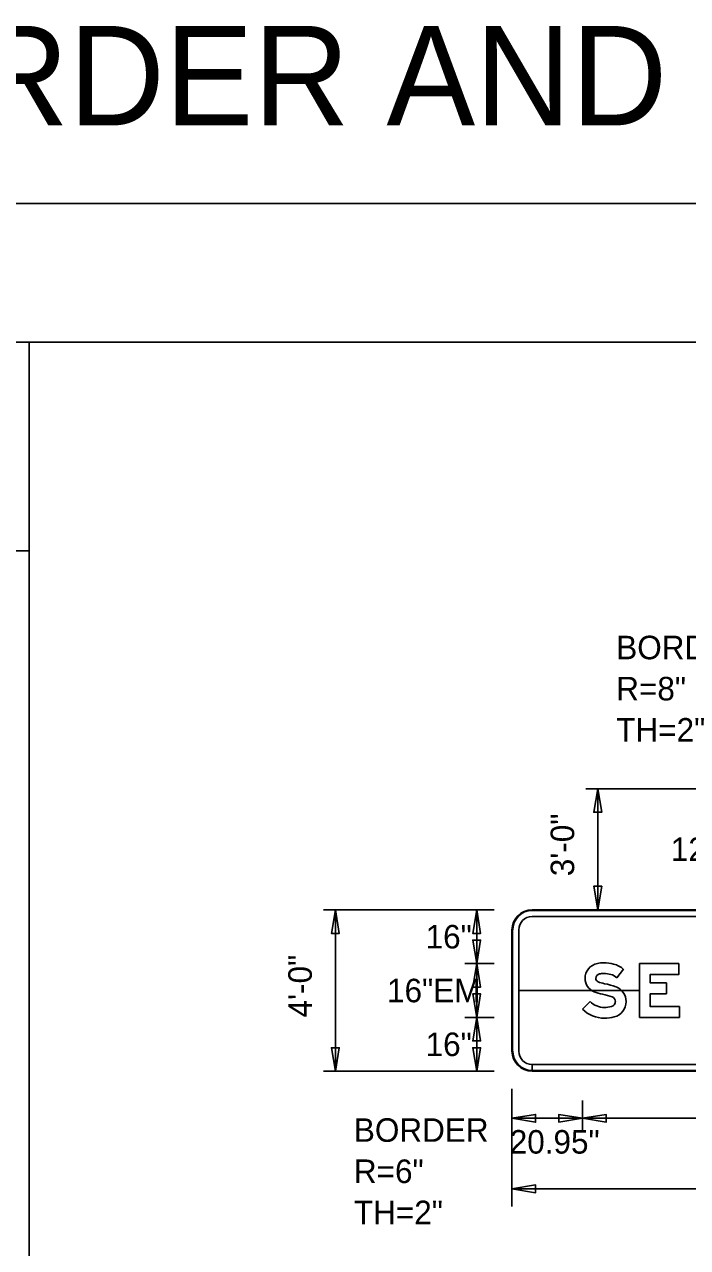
# Model space of a CAD drawing. Extents: x 2149934 to 2150188, y 145114 to 145238.
# Drawn here: x 2150076.2 to 2150092.63, y 145194.08 to 145224.38 of the extents above; entities that cross this region are included whole.
import ezdxf

# ---------------------------------------------------------------- set-up
doc = ezdxf.new("R2010")
doc.units = 0
for name, color, linetype in [('BORDER', 7, 'Continuous'), ('GSBWFILL', 7, 'Continuous'), ('GSCOLORFILL', 7, 'Continuous'), ('GSDIMS', 7, 'Continuous'), ('GSOUTLINE', 7, 'Continuous'), ('Level 1', 7, 'Continuous'), ('NON-PLOT', 7, 'Continuous'), ('PDF', 7, 'Continuous'), ('TEXT', 7, 'Continuous')]:
    doc.layers.add(name, color=color, linetype=linetype)

msp = doc.modelspace()

# ---------------------------------------------------------------- linework, layer by layer
at = {"layer": 'BORDER'}
for p, q in [((2150010.458, 145219.948), (2150174.061, 145219.948)), ((2150171.536, 145216.512), (2150017.557, 145216.512))]:
    msp.add_line(p, q, dxfattribs=at)
at = {"layer": 'GSBWFILL'}
for p, q in [((2150107.279, 145202.445), (2150088.779, 145202.445)), ((2150088.779, 145202.278), (2150107.279, 145202.278)), ((2150088.279, 145201.945), (2150088.279, 145198.945)), ((2150088.445, 145198.945), (2150088.445, 145201.945)), ((2150088.779, 145198.445), (2150088.779, 145198.611)), ((2150107.279, 145198.611), (2150088.78, 145198.611)), ((2150088.78, 145198.611), (2150088.78, 145198.445)), ((2150088.78, 145198.445), (2150107.279, 145198.445))]:
    msp.add_line(p, q, dxfattribs=at)
for points in [[(2150090.879, 145200.759), (2150091.044, 145200.97)], [(2150090.214, 145200.17), (2150090.026, 145199.981)]]:
    msp.add_lwpolyline(points, dxfattribs=at)
msp.add_lwpolyline([(2150092.413, 145201.111), (2150092.413, 145200.845), (2150091.706, 145200.845), (2150091.706, 145200.631), (2150092.106, 145200.631), (2150092.106, 145200.365), (2150091.706, 145200.365), (2150091.706, 145200.045), (2150092.426, 145200.045), (2150092.426, 145199.778), (2150091.439, 145199.778), (2150091.439, 145201.111)], close=True, dxfattribs=at)
for centre, radius, start, end in [((2150088.779, 145201.945), 0.5, 90, 180), ((2150088.779, 145201.945), 0.333, 90, 180), ((2150088.779, 145198.945), 0.5, 180, 270), ((2150088.779, 145198.945), 0.333, 180, 270)]:
    msp.add_arc(centre, radius, start, end, dxfattribs=at)
for centre, major_axis, start_param, end_param in [((2150090.471, 145200.742), (0, 0.382), 0.202758, 1.570796), ((2150090.553, 145200.347), (0, 0.785), 0, 0.202758), ((2150090.553, 145200.169), (0, 0.963), 6.026234, 6.283185), ((2150090.642, 145200.509), (0, 0.611), 5.565152, 6.026234), ((2150090.443, 145200.742), (0, 0.354), 1.570796, 2.761249), ((2150090.471, 145200.742), (0, 0.115), 0.202758, 1.570796), ((2150090.443, 145200.742), (0, 0.0872), 1.570796, 2.761249), ((2150090.734, 145201.469), (0, 0.87), 2.761249, 2.95744), ((2150090.553, 145200.347), (0, 0.519), 0, 0.202758), ((2150090.553, 145200.169), (0, 0.697), 6.026234, 6.283185), ((2150090.277, 145199.018), (0, 1.623), 5.918637, 6.099033), ((2150090.642, 145200.509), (0, 0.345), 5.523837, 6.026234), ((2150090.734, 145201.469), (0, 1.137), 2.761249, 2.95744), ((2150090.277, 145199.018), (0, 1.357), 5.918637, 6.099033), ((2150090.718, 145200.172), (0, 0.388), 4.712389, 5.918637), ((2150090.569, 145200.528), (0, 0.504), 2.360607, 3.141593), ((2150090.569, 145200.702), (0, 0.678), 3.141593, 3.401517), ((2150090.71, 145200.172), (0, 0.129), 3.401517, 4.712389), ((2150090.718, 145200.172), (0, 0.122), 4.712389, 5.918637), ((2150090.71, 145200.172), (0, 0.396), 3.401517, 4.712389), ((2150090.569, 145200.528), (0, 0.771), 2.360607, 3.141593), ((2150090.569, 145200.702), (0, 0.945), 3.141593, 3.401517)]:
    msp.add_ellipse(centre, major_axis=major_axis, ratio=0.999996, start_param=start_param, end_param=end_param, dxfattribs=at)
at = {"layer": 'GSCOLORFILL'}
for p, q in [((2150107.279, 145202.445), (2150088.779, 145202.445)), ((2150107.279, 145202.445), (2150088.779, 145202.445)), ((2150107.279, 145202.445), (2150088.779, 145202.445)), ((2150088.779, 145202.428), (2150107.279, 145202.428)), ((2150088.779, 145202.278), (2150107.279, 145202.278)), ((2150088.279, 145201.945), (2150088.279, 145198.945)), ((2150088.279, 145201.945), (2150088.279, 145198.945)), ((2150088.279, 145201.945), (2150088.279, 145198.945)), ((2150088.295, 145198.945), (2150088.295, 145201.945)), ((2150088.445, 145198.945), (2150088.445, 145201.945)), ((2150088.779, 145198.445), (2150088.779, 145198.611)), ((2150107.279, 145198.611), (2150088.78, 145198.611)), ((2150088.78, 145198.611), (2150088.78, 145198.445)), ((2150088.779, 145198.445), (2150088.779, 145198.461)), ((2150107.279, 145198.461), (2150088.779, 145198.461)), ((2150088.779, 145198.461), (2150088.779, 145198.445)), ((2150088.779, 145198.445), (2150107.279, 145198.445)), ((2150088.779, 145198.445), (2150107.279, 145198.445)), ((2150088.78, 145198.445), (2150107.279, 145198.445))]:
    msp.add_line(p, q, dxfattribs=at)
for points in [[(2150090.879, 145200.759), (2150091.044, 145200.97)], [(2150090.214, 145200.17), (2150090.026, 145199.981)]]:
    msp.add_lwpolyline(points, dxfattribs=at)
msp.add_lwpolyline([(2150092.413, 145201.111), (2150092.413, 145200.845), (2150091.706, 145200.845), (2150091.706, 145200.631), (2150092.106, 145200.631), (2150092.106, 145200.365), (2150091.706, 145200.365), (2150091.706, 145200.045), (2150092.426, 145200.045), (2150092.426, 145199.778), (2150091.439, 145199.778), (2150091.439, 145201.111)], close=True, dxfattribs=at)
for centre, radius, start, end in [((2150088.779, 145201.945), 0.5, 90, 180), ((2150088.779, 145201.945), 0.5, 90, 180), ((2150088.779, 145201.945), 0.5, 90, 180), ((2150088.779, 145201.945), 0.483, 90, 180), ((2150088.779, 145201.945), 0.333, 90, 180), ((2150088.779, 145198.945), 0.5, 180, 270), ((2150088.779, 145198.945), 0.5, 180, 270), ((2150088.779, 145198.945), 0.5, 180, 270), ((2150088.779, 145198.945), 0.483, 180, 270), ((2150088.779, 145198.945), 0.333, 180, 270)]:
    msp.add_arc(centre, radius, start, end, dxfattribs=at)
for centre, major_axis, start_param, end_param in [((2150090.471, 145200.742), (0, 0.382), 0.202758, 1.570796), ((2150090.553, 145200.347), (0, 0.785), 0, 0.202758), ((2150090.553, 145200.169), (0, 0.963), 6.026234, 6.283185), ((2150090.642, 145200.509), (0, 0.611), 5.565152, 6.026234), ((2150090.443, 145200.742), (0, 0.354), 1.570796, 2.761249), ((2150090.471, 145200.742), (0, 0.115), 0.202758, 1.570796), ((2150090.443, 145200.742), (0, 0.0872), 1.570796, 2.761249), ((2150090.734, 145201.469), (0, 0.87), 2.761249, 2.95744), ((2150090.553, 145200.347), (0, 0.519), 0, 0.202758), ((2150090.553, 145200.169), (0, 0.697), 6.026234, 6.283185), ((2150090.277, 145199.018), (0, 1.623), 5.918637, 6.099033), ((2150090.642, 145200.509), (0, 0.345), 5.523837, 6.026234), ((2150090.734, 145201.469), (0, 1.137), 2.761249, 2.95744), ((2150090.277, 145199.018), (0, 1.357), 5.918637, 6.099033), ((2150090.718, 145200.172), (0, 0.388), 4.712389, 5.918637), ((2150090.569, 145200.528), (0, 0.504), 2.360607, 3.141593), ((2150090.569, 145200.702), (0, 0.678), 3.141593, 3.401517), ((2150090.71, 145200.172), (0, 0.129), 3.401517, 4.712389), ((2150090.718, 145200.172), (0, 0.122), 4.712389, 5.918637), ((2150090.71, 145200.172), (0, 0.396), 3.401517, 4.712389), ((2150090.569, 145200.528), (0, 0.771), 2.360607, 3.141593), ((2150090.569, 145200.702), (0, 0.945), 3.141593, 3.401517)]:
    msp.add_ellipse(centre, major_axis=major_axis, ratio=0.999996, start_param=start_param, end_param=end_param, dxfattribs=at)
at = {"layer": 'GSDIMS'}
for p, q in [((2150090.841, 145205.445), (2150090.112, 145205.445)), ((2150090.403, 145202.445), (2150090.403, 145205.445)), ((2150094.341, 145205.445), (2150090.841, 145205.445)), ((2150084.341, 145202.445), (2150083.612, 145202.445)), ((2150083.904, 145198.445), (2150083.904, 145202.445)), ((2150087.841, 145202.445), (2150084.341, 145202.445)), ((2150087.841, 145202.445), (2150087.112, 145202.445)), ((2150087.404, 145201.111), (2150087.404, 145202.445)), ((2150090.841, 145202.445), (2150090.112, 145202.445)), ((2150094.341, 145202.445), (2150090.841, 145202.445)), ((2150087.841, 145201.111), (2150087.112, 145201.111)), ((2150087.841, 145201.111), (2150087.112, 145201.111)), ((2150087.404, 145201.111), (2150087.404, 145199.778)), ((2150087.841, 145199.778), (2150087.112, 145199.778)), ((2150087.841, 145199.778), (2150087.112, 145199.778)), ((2150087.404, 145198.445), (2150087.404, 145199.778)), ((2150084.341, 145198.445), (2150083.612, 145198.445)), ((2150087.841, 145198.445), (2150084.341, 145198.445)), ((2150087.841, 145198.445), (2150087.112, 145198.445)), ((2150088.279, 145198.007), (2150088.279, 145195.091)), ((2150088.279, 145197.716), (2150088.279, 145196.986)), ((2150090.026, 145197.716), (2150090.026, 145196.986)), ((2150090.026, 145197.716), (2150090.026, 145196.986)), ((2150088.279, 145197.278), (2150090.026, 145197.278)), ((2150090.026, 145197.278), (2150106.031, 145197.278)), ((2150088.279, 145195.966), (2150088.279, 145195.236)), ((2150088.279, 145195.528), (2150107.779, 145195.528))]:
    msp.add_line(p, q, dxfattribs=at)
for points in [[(2150090.403, 145205.445), (2150090.501, 145204.862), (2150090.306, 145204.862)], [(2150090.403, 145202.445), (2150090.501, 145203.028), (2150090.306, 145203.028)], [(2150083.904, 145202.445), (2150084.001, 145201.861), (2150083.806, 145201.861)], [(2150087.404, 145202.445), (2150087.501, 145201.861), (2150087.306, 145201.861)], [(2150087.404, 145201.111), (2150087.501, 145201.695), (2150087.306, 145201.695)], [(2150087.404, 145201.111), (2150087.501, 145200.528), (2150087.306, 145200.528)], [(2150087.404, 145199.778), (2150087.501, 145200.361), (2150087.306, 145200.361)], [(2150087.404, 145199.778), (2150087.501, 145199.195), (2150087.306, 145199.195)], [(2150083.904, 145198.445), (2150084.001, 145199.028), (2150083.806, 145199.028)], [(2150087.404, 145198.445), (2150087.501, 145199.028), (2150087.306, 145199.028)], [(2150088.279, 145197.278), (2150088.862, 145197.375), (2150088.862, 145197.181)], [(2150090.026, 145197.278), (2150089.443, 145197.375), (2150089.443, 145197.181)], [(2150090.026, 145197.278), (2150090.609, 145197.375), (2150090.609, 145197.181)], [(2150088.279, 145195.528), (2150088.862, 145195.625), (2150088.862, 145195.431)]]:
    msp.add_lwpolyline(points, close=True, dxfattribs=at)
at = {"layer": 'GSOUTLINE'}
for p, q in [((2150107.279, 145202.445), (2150088.779, 145202.445)), ((2150107.279, 145202.278), (2150088.779, 145202.278)), ((2150088.279, 145201.945), (2150088.279, 145198.945)), ((2150088.445, 145201.945), (2150088.445, 145198.945)), ((2150088.779, 145198.611), (2150107.279, 145198.611)), ((2150088.779, 145198.445), (2150107.279, 145198.445))]:
    msp.add_line(p, q, dxfattribs=at)
for points in [[(2150090.879, 145200.759), (2150091.044, 145200.97)], [(2150090.214, 145200.17), (2150090.026, 145199.981)]]:
    msp.add_lwpolyline(points, dxfattribs=at)
msp.add_lwpolyline([(2150092.413, 145201.111), (2150092.413, 145200.845), (2150091.706, 145200.845), (2150091.706, 145200.631), (2150092.106, 145200.631), (2150092.106, 145200.365), (2150091.706, 145200.365), (2150091.706, 145200.045), (2150092.426, 145200.045), (2150092.426, 145199.778), (2150091.439, 145199.778), (2150091.439, 145201.111)], close=True, dxfattribs=at)
for centre, radius, start, end in [((2150088.779, 145201.945), 0.5, 90, 180), ((2150088.779, 145201.945), 0.333, 90, 180), ((2150088.779, 145198.945), 0.5, 180, 270), ((2150088.779, 145198.945), 0.333, 180, 270)]:
    msp.add_arc(centre, radius, start, end, dxfattribs=at)
for centre, major_axis, start_param, end_param in [((2150090.471, 145200.742), (0, 0.382), 0.202758, 1.570796), ((2150090.553, 145200.347), (0, 0.785), 0, 0.202758), ((2150090.553, 145200.169), (0, 0.963), 6.026234, 6.283185), ((2150090.642, 145200.509), (0, 0.611), 5.565152, 6.026234), ((2150090.443, 145200.742), (0, 0.354), 1.570796, 2.761249), ((2150090.471, 145200.742), (0, 0.115), 0.202758, 1.570796), ((2150090.443, 145200.742), (0, 0.0872), 1.570796, 2.761249), ((2150090.734, 145201.469), (0, 0.87), 2.761249, 2.95744), ((2150090.553, 145200.347), (0, 0.519), 0, 0.202758), ((2150090.553, 145200.169), (0, 0.697), 6.026234, 6.283185), ((2150090.277, 145199.018), (0, 1.623), 5.918637, 6.099033), ((2150090.642, 145200.509), (0, 0.345), 5.523837, 6.026234), ((2150090.734, 145201.469), (0, 1.137), 2.761249, 2.95744), ((2150090.277, 145199.018), (0, 1.357), 5.918637, 6.099033), ((2150090.718, 145200.172), (0, 0.388), 4.712389, 5.918637), ((2150090.569, 145200.528), (0, 0.504), 2.360607, 3.141593), ((2150090.569, 145200.702), (0, 0.678), 3.141593, 3.401517), ((2150090.71, 145200.172), (0, 0.129), 3.401517, 4.712389), ((2150090.718, 145200.172), (0, 0.122), 4.712389, 5.918637), ((2150090.71, 145200.172), (0, 0.396), 3.401517, 4.712389), ((2150090.569, 145200.528), (0, 0.771), 2.360607, 3.141593), ((2150090.569, 145200.702), (0, 0.945), 3.141593, 3.401517)]:
    msp.add_ellipse(centre, major_axis=major_axis, ratio=0.999996, start_param=start_param, end_param=end_param, dxfattribs=at)
at = {"layer": 'Level 1'}
for p, q in [((2150076.316, 145216.512), (2150076.316, 145117.388)), ((2150062.21, 145211.34), (2150076.316, 145211.34))]:
    msp.add_line(p, q, dxfattribs=at)
at = {"layer": 'NON-PLOT'}
msp.add_line((2150088.445, 145200.445), (2150091.439, 145200.445), dxfattribs=at)
at = {"layer": 'PDF'}
msp.add_lwpolyline([(2150010.458, 145114.088), (2150174.061, 145114.088), (2150174.061, 145219.948), (2150010.458, 145219.948)], close=True, dxfattribs=at)

# ---------------------------------------------------------------- texts
at = {"layer": 'GSDIMS'}
for s, p in [('BORDER', (2150090.862, 145208.653)), ('R=8"', (2150090.862, 145207.633)), ('TH=2"', (2150090.862, 145206.612)), ('12"E', (2150092.213, 145203.653)), ('16"', (2150086.139, 145201.486)), ('16"EM', (2150085.183, 145200.153)), ('16"', (2150086.139, 145198.82)), ('BORDER', (2150084.362, 145196.695)), ('20.95"', (2150088.223, 145196.403)), ('R=6"', (2150084.362, 145195.674)), ('TH=2"', (2150084.362, 145194.653))]:
    msp.add_text(s, height=0.5833, dxfattribs=at).set_placement(p)
for s, p in [('3\'-0"', (2150089.82, 145203.277)), ('4\'-0"', (2150083.32, 145199.777))]:
    msp.add_text(s, height=0.5833, rotation=90, dxfattribs=at).set_placement(p)
at = {"layer": 'TEXT'}
msp.add_text('BORDER AND REPORT 70 SCALE', height=2.46401, dxfattribs=at).set_placement((2150070.157, 145221.883))

doc.saveas('drawing.dxf')
